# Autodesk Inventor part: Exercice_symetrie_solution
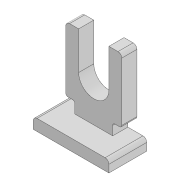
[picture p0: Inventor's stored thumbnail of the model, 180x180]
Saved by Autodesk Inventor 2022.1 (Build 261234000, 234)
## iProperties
Created: 2021-03
Part Number: Exercice_symetrie_solution
Material: Générique
Document SubType Name: Modeling
Designer: Fabian
Mass: 162.483 g
Surface Area: 302.936 cm^2
Volume: 162.483 cm^3
Density: 1 g/cm^3
Appearance: Par défaut
Author: Fabian
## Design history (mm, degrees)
sketch "Esquisse1"
  geometry: L1 (-20, 0)-(-20, 50); L2 (-20, 50)-(-37, 50); L3 (-37, 50)-(-37, -35); L4 (-37, -35)-(-25, -35); L5 (-25, -35)-(-25, -50); L6 (-25, -50)-(-50, -50); L7 (-50, -50)-(-50, -65); L8 (-50, -65)-(0, -65); L9 (0, 50)-(0, -65); L10 (-25, -50)-(0, -50); A1 r 20 centre (0, 0) between (-20, 0) and (0, -20); 2 further points
  constraints: 21 end point, 6 perpendicular, 4 point on line, 3 vertical, 2 point on circle, 1 centre point, 1 coincident, 1 horizontal, 1 midpoint, 1 tangent
  dimensions: "d0" = 40 diameter of A1; "d1" = 74 diameter of L3 L9; "d2" = 115 distance between parallel lines of L8 L2; "d3" = 30 distance between parallel lines of L8 L4; "d4" = 15 distance of L6.end L7.end; "d5" = 100 diameter of L7 L9; "d6" = 50 diameter of L5 L9; "d7" = 65 distance from line of L8 point (0, 0)
extrude "Extrusion1" new body sketch "Esquisse1" distance "d8" = 20; taper "d9" = 0 deg
extrude "Extrusion3" join sketch "Esquisse1" distance "d22" = 50; taper "d23" = 0 deg
fillet "Congé2" dims "d24" = 5, "d25" = 3
mirror "Symétrie2"
node "Solide1"
